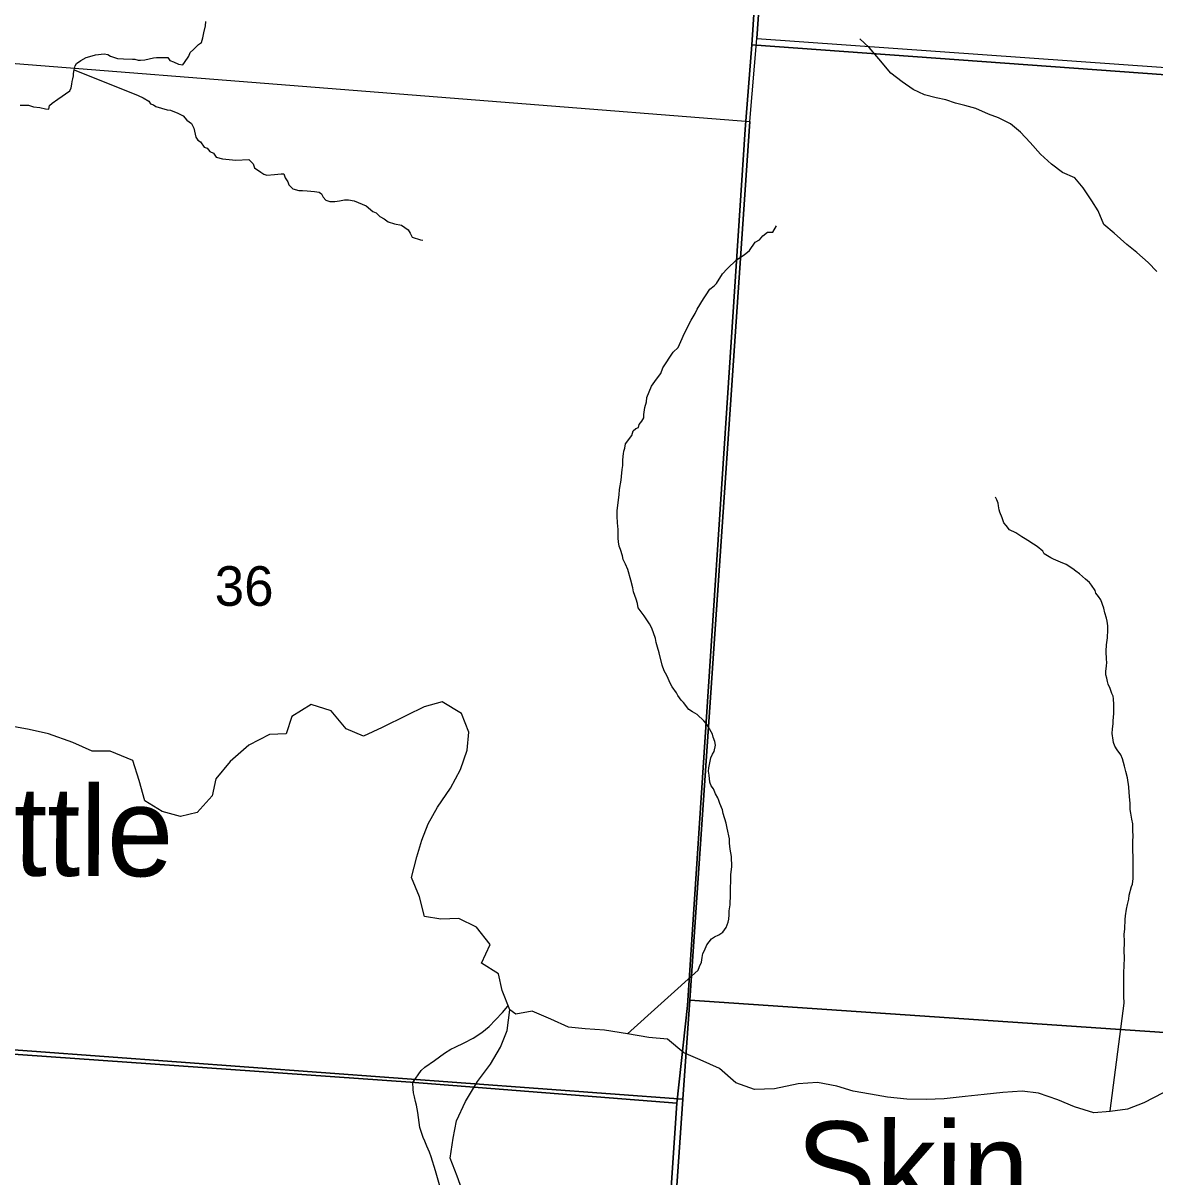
# Model space of a CAD drawing. Extents: x 0 to 34, y 0 to 22.
# Drawn here: x 6.132 to 7.329, y 19.223 to 20.443 of the extents above; entities that cross this region are included whole.
import ezdxf

# ---------------------------------------------------------------- set-up
doc = ezdxf.new("R2010")
doc.units = 0
for name, color, linetype in [('GM_X_Corporation', 7, 'Continuous'), ('GM_X_Minor_River', 7, 'Continuous'), ('GM_X_Minor_River_Text', 7, 'Continuous'), ('GM_X_Section_Text', 7, 'Continuous'), ('GM_X_Township_Road', 7, 'Continuous')]:
    doc.layers.add(name, color=color, linetype=linetype)

msp = doc.modelspace()

# ---------------------------------------------------------------- linework, layer by layer
at = {"layer": 'GM_X_Corporation'}
for points in [[(6.9348, 20.9), (2.1, 20.9), (2.1, 19.6396), (2.105, 19.6393), (2.5886, 19.6074), (3.0215, 19.5789), (3.8201, 19.5262), (3.8692, 19.5228), (4.8375, 19.4557), (5.0201, 19.4401), (5.6539, 19.3859), (5.9419, 19.3649), (6.5423, 19.3229), (6.824, 19.3005), (6.835, 19.4037), (6.8961, 20.3303), (6.9032, 20.4198)], [(6.9414, 20.9), (5.9334, 20.9), (5.901, 20.4176), (6.9011, 20.3385), (6.9084, 20.4264)], [(8.9, 20.2763), (8.9, 20.9), (6.9348, 20.9), (6.9032, 20.4198), (8.0028, 20.34), (8.3805, 20.3169), (8.59, 20.3005)], [(8.4295, 20.9), (6.9414, 20.9), (6.9084, 20.4264), (8.0074, 20.3484), (8.3851, 20.3217)], [(6.9084, 20.4264), (8.0074, 20.3484), (7.9347, 19.3346), (6.8376, 19.4096), (6.9011, 20.3385)], [(6.9011, 20.3385), (6.8376, 19.4096), (6.8303, 19.3047), (5.8355, 19.3781), (5.901, 20.4176)], [(8.9, 16.2015), (8.9, 20.2763), (8.59, 20.3005), (8.3805, 20.3169), (8.0028, 20.34), (6.9032, 20.4198), (6.8961, 20.3303), (6.835, 19.4037), (6.824, 19.3005), (6.7876, 18.7583), (6.7629, 18.3924), (6.7536, 18.2991), (6.7043, 17.4985), (6.6962, 17.3669), (6.6852, 17.2401), (6.6249, 16.3344), (7.5782, 16.28), (7.7162, 16.2721), (7.873, 16.2628)], [(7.9347, 19.3346), (7.864, 18.3242), (6.7676, 18.3985), (6.8303, 19.3047), (6.8376, 19.4096)], [(5.8355, 19.3781), (6.8303, 19.3047), (6.7676, 18.3985), (6.7615, 18.3053), (5.775, 18.3681)]]:
    msp.add_lwpolyline(points, close=True, dxfattribs=at)
msp.add_lwpolyline([(6.7043, 17.4985), (6.7536, 18.2991), (6.7629, 18.3924), (6.7876, 18.7583), (6.824, 19.3005), (6.5423, 19.3229), (5.9419, 19.3649), (5.6539, 19.3859), (5.0201, 19.4401), (4.8375, 19.4557), (3.8692, 19.5228), (3.8201, 19.5262), (3.0215, 19.5789), (2.5886, 19.6074), (2.105, 19.6393), (2.1, 19.6396), (2.1, 16.1353)], dxfattribs=at)
at = {"layer": 'GM_X_Minor_River'}
for points in [[(6.1294, 20.3559), (6.1382, 20.3558), (6.1434, 20.3541), (6.1502, 20.3533), (6.1563, 20.352), (6.1597, 20.3516), (6.1605, 20.3554), (6.1632, 20.358), (6.1693, 20.3621), (6.182, 20.371), (6.1832, 20.3744), (6.184, 20.3781), (6.1844, 20.3808), (6.1849, 20.3838), (6.1857, 20.3869), (6.1857, 20.3895), (6.1865, 20.3933), (6.1877, 20.3975), (6.1889, 20.4001), (6.1935, 20.4031), (6.1993, 20.4064), (6.2054, 20.4082), (6.2092, 20.4092), (6.2183, 20.4102), (6.222, 20.4094), (6.225, 20.4078), (6.2322, 20.4054), (6.2386, 20.4049), (6.2481, 20.4044), (6.2507, 20.4044), (6.2541, 20.4035), (6.2568, 20.4035), (6.2613, 20.4038), (6.2705, 20.4059), (6.2735, 20.4062), (6.278, 20.4062), (6.2856, 20.4064), (6.2878, 20.4033), (6.2916, 20.4018), (6.2969, 20.3994), (6.3014, 20.3986), (6.303, 20.4012), (6.3076, 20.4079), (6.3092, 20.4117), (6.3127, 20.4147), (6.3181, 20.4199), (6.3211, 20.4221), (6.3227, 20.4271), (6.3236, 20.4324), (6.3252, 20.4399), (6.3257, 20.4445)], [(7.3315, 20.1801), (7.3224, 20.1896), (7.3103, 20.2002), (7.2997, 20.2085), (7.2865, 20.2206), (7.2755, 20.2297), (7.2694, 20.2441), (7.2626, 20.2547), (7.2535, 20.2684), (7.2448, 20.279), (7.2316, 20.2847), (7.2202, 20.2937), (7.2085, 20.304), (7.1975, 20.3165), (7.1873, 20.3275), (7.1767, 20.3362), (7.1642, 20.3426), (7.1536, 20.3464), (7.14, 20.3525), (7.1283, 20.3555), (7.1184, 20.3582), (7.1082, 20.3616), (7.098, 20.3638), (7.0859, 20.3669), (7.0738, 20.3726), (7.0621, 20.3805), (7.05, 20.3896), (7.0375, 20.4048), (7.0273, 20.4169), (7.0174, 20.426)], [(6.1865, 20.3933), (6.2542, 20.3663), (6.2595, 20.3636), (6.2655, 20.36), (6.2673, 20.3574), (6.2703, 20.3562), (6.273, 20.3546), (6.2847, 20.351), (6.2884, 20.3505), (6.296, 20.3474), (6.3016, 20.3446), (6.3057, 20.34), (6.3105, 20.3365), (6.3131, 20.3315), (6.3152, 20.322), (6.3174, 20.3189), (6.32, 20.317), (6.3241, 20.3116), (6.3271, 20.3104), (6.3301, 20.3069), (6.3338, 20.305), (6.3368, 20.3011), (6.3432, 20.2991), (6.3576, 20.2977), (6.3712, 20.2986), (6.3757, 20.294), (6.3771, 20.2898), (6.3839, 20.2851), (6.3869, 20.2828), (6.3903, 20.282), (6.3982, 20.2826), (6.4054, 20.2832), (6.4081, 20.2832), (6.4095, 20.279), (6.4125, 20.2748), (6.4136, 20.2717), (6.4176, 20.2675), (6.4241, 20.2658), (6.4278, 20.2658), (6.4328, 20.2653), (6.4407, 20.2648), (6.4456, 20.2639), (6.4482, 20.262), (6.4497, 20.2585), (6.4527, 20.2555), (6.4568, 20.2542), (6.4621, 20.2542), (6.467, 20.2548), (6.4724, 20.2559), (6.4765, 20.2558), (6.4826, 20.2546), (6.4954, 20.2494), (6.5025, 20.2436), (6.5058, 20.242), (6.5099, 20.2382), (6.5144, 20.2358), (6.5185, 20.2327), (6.5253, 20.2303), (6.5325, 20.229), (6.5362, 20.2267), (6.5396, 20.224), (6.5418, 20.2205), (6.544, 20.2163), (6.5527, 20.2135), (6.5552, 20.2131)], [(6.7653, 19.9634), (6.7662, 19.9706), (6.7666, 19.9748), (6.7667, 19.9801), (6.7672, 19.9846), (6.7676, 19.9873), (6.7677, 19.9899), (6.7689, 19.9933), (6.7697, 19.9979), (6.7763, 20.0065), (6.7775, 20.0114), (6.7806, 20.014), (6.7833, 20.0151), (6.7841, 20.0181), (6.7868, 20.0219), (6.7888, 20.0253), (6.7888, 20.0287), (6.7901, 20.0363), (6.7917, 20.0423), (6.7922, 20.0469), (6.7969, 20.0589), (6.8023, 20.0661), (6.807, 20.0721), (6.809, 20.0781), (6.8199, 20.0946), (6.8253, 20.0995), (6.828, 20.1059), (6.832, 20.1149), (6.839, 20.1285), (6.8433, 20.1356), (6.8453, 20.1402), (6.8519, 20.1511), (6.855, 20.1552), (6.8589, 20.1612), (6.8632, 20.1649), (6.8659, 20.1672), (6.8721, 20.1777), (6.8771, 20.1829), (6.8868, 20.1922), (6.8952, 20.1978), (6.9006, 20.2023), (6.9068, 20.2109), (6.9114, 20.2135), (6.9149, 20.2176), (6.9199, 20.2217), (6.9252, 20.2216), (6.9291, 20.2284)], [(6.7715, 19.3738), (6.8463, 19.4413), (6.8479, 19.445), (6.8498, 19.4496), (6.8507, 19.4545), (6.8515, 19.4587), (6.8531, 19.462), (6.8555, 19.4681), (6.8605, 19.4745), (6.8636, 19.4763), (6.8681, 19.4785), (6.8724, 19.4815), (6.8759, 19.4863), (6.8782, 19.492), (6.8787, 19.495), (6.8791, 19.4996), (6.8792, 19.5041), (6.8801, 19.5102), (6.8806, 19.5212), (6.881, 19.5425), (6.8819, 19.5504), (6.8817, 19.5615), (6.8803, 19.5691), (6.8797, 19.5755), (6.8794, 19.5801), (6.8769, 19.5912), (6.8759, 19.5965), (6.873, 19.6068), (6.872, 19.6106), (6.8694, 19.6175), (6.8684, 19.6206), (6.8673, 19.6236), (6.8647, 19.6275), (6.8625, 19.6328), (6.8603, 19.6363), (6.8589, 19.6401), (6.8579, 19.6473), (6.8575, 19.6515), (6.8576, 19.6553), (6.8597, 19.6659), (6.8617, 19.6697), (6.8632, 19.6723), (6.8649, 19.6791), (6.8642, 19.6829), (6.8623, 19.6875), (6.8616, 19.6909), (6.8569, 19.699), (6.8547, 19.7021), (6.8524, 19.7048), (6.8453, 19.7114), (6.8405, 19.7145), (6.8367, 19.7168), (6.8308, 19.7241), (6.8286, 19.7268), (6.8249, 19.7318), (6.8234, 19.7345), (6.819, 19.7407), (6.8171, 19.7441), (6.8131, 19.7529), (6.8106, 19.7579), (6.8084, 19.7636), (6.8052, 19.7766), (6.8034, 19.7827), (6.802, 19.7877), (6.8013, 19.7919), (6.7973, 19.8029), (6.7948, 19.8075), (6.7892, 19.816), (6.7829, 19.8245), (6.7823, 19.829), (6.7808, 19.8336), (6.7779, 19.8413), (6.7773, 19.8454), (6.7751, 19.8535), (6.7719, 19.8649), (6.7694, 19.8706), (6.7672, 19.8756), (6.7665, 19.8794), (6.7643, 19.8859), (6.7629, 19.8897), (6.7622, 19.8943), (6.7619, 19.8981), (6.7617, 19.9072), (6.761, 19.9141), (6.7608, 19.9213), (6.7609, 19.9274), (6.7627, 19.9437), (6.7632, 19.9494), (6.7649, 19.9592), (6.7653, 19.9634)], [(7.2109, 19.8844), (7.2049, 19.8891), (7.2012, 19.8918), (7.1952, 19.8957), (7.1922, 19.8973), (7.1888, 19.8996), (7.1824, 19.9035), (7.1757, 19.907), (7.1723, 19.9113), (7.1697, 19.9143), (7.1679, 19.9197), (7.1654, 19.9254), (7.1647, 19.9281), (7.164, 19.9323), (7.1637, 19.935), (7.1622, 19.9384), (7.1608, 19.9413)], [(7.2822, 19.2925), (7.2968, 19.4062), (7.2965, 19.4138), (7.2967, 19.426), (7.2965, 19.4363), (7.2966, 19.4401), (7.2971, 19.4442), (7.2973, 19.4556), (7.297, 19.4602), (7.2972, 19.472), (7.2969, 19.4788), (7.2978, 19.4849), (7.298, 19.4947), (7.2984, 19.4985), (7.2993, 19.5057), (7.3005, 19.5106), (7.3017, 19.5163), (7.3022, 19.5205), (7.3046, 19.5296), (7.3058, 19.5322), (7.3063, 19.5383), (7.3066, 19.5561), (7.3063, 19.5622), (7.306, 19.5668), (7.3061, 19.5713), (7.3062, 19.5782), (7.3063, 19.5823), (7.3061, 19.5896), (7.3062, 19.596), (7.3051, 19.601), (7.3041, 19.6071), (7.3034, 19.6112), (7.3031, 19.6177), (7.3028, 19.6211), (7.3022, 19.6291), (7.3019, 19.6352), (7.3006, 19.6447), (7.2988, 19.6512), (7.2974, 19.6569), (7.2953, 19.6646), (7.2934, 19.6688), (7.2897, 19.6742), (7.2872, 19.678), (7.2857, 19.6818), (7.2854, 19.6845), (7.2844, 19.6913), (7.2845, 19.6963), (7.2853, 19.7016), (7.2854, 19.705), (7.2859, 19.7126), (7.286, 19.7221), (7.2858, 19.7282), (7.2854, 19.7308), (7.284, 19.7339), (7.2822, 19.7392), (7.28, 19.7438), (7.2793, 19.7465), (7.2786, 19.7499), (7.2775, 19.7534), (7.2776, 19.7575), (7.2784, 19.7625), (7.2785, 19.767), (7.2782, 19.7697), (7.2779, 19.7784), (7.2784, 19.7853), (7.2793, 19.7928), (7.2795, 19.8012), (7.2796, 19.8054), (7.2789, 19.8103), (7.2782, 19.8134), (7.2764, 19.8191), (7.2753, 19.8241), (7.2721, 19.8328), (7.2699, 19.8363), (7.2669, 19.8398), (7.2662, 19.8428), (7.2625, 19.8482), (7.2603, 19.8513), (7.2562, 19.8548), (7.2498, 19.8602), (7.2457, 19.8633), (7.2427, 19.8656), (7.2356, 19.8703), (7.2296, 19.8727), (7.2221, 19.8759), (7.2195, 19.8774), (7.2123, 19.8813), (7.2109, 19.8844)], [(6.5999, 19.1999), (6.5916, 19.2234), (6.5841, 19.2424), (6.5872, 19.2636), (6.591, 19.2818), (6.6002, 19.3023), (6.6131, 19.3235), (6.6268, 19.3417), (6.6374, 19.3598), (6.6443, 19.3773), (6.6474, 19.3992), (6.6391, 19.4198), (6.6354, 19.4372), (6.6173, 19.4486), (6.6264, 19.4683), (6.6121, 19.4866), (6.5932, 19.4957), (6.5743, 19.495), (6.5569, 19.4981), (6.5516, 19.5186), (6.5434, 19.5391), (6.5487, 19.5611), (6.5541, 19.5785), (6.561, 19.596), (6.5709, 19.6134), (6.5846, 19.6338), (6.5952, 19.6535), (6.6021, 19.674), (6.6037, 19.6929), (6.5962, 19.7127), (6.5758, 19.7249), (6.5568, 19.7196), (6.5379, 19.7106), (6.5121, 19.6977), (6.4924, 19.6887), (6.4742, 19.6963), (6.4584, 19.7154), (6.4372, 19.7222), (6.4167, 19.7094), (6.4106, 19.6912), (6.3932, 19.6905), (6.3712, 19.6792), (6.3515, 19.6618), (6.3363, 19.6437), (6.3325, 19.6255), (6.3165, 19.6081), (6.2991, 19.6036), (6.2794, 19.6089), (6.2613, 19.6204), (6.2553, 19.6416), (6.2485, 19.6629), (6.2244, 19.6728), (6.2054, 19.6729), (6.185, 19.682), (6.1593, 19.6912), (6.1389, 19.6958), (6.1177, 19.6997)], [(6.8138, 19.3684), (6.7942, 19.37), (6.7715, 19.3738), (6.7473, 19.3777), (6.7268, 19.3793), (6.7094, 19.3809), (6.6905, 19.3893), (6.6709, 19.3977), (6.6534, 19.3947), (6.6474, 19.3992)], [(7.3382, 19.3115), (7.3178, 19.3009), (7.3003, 19.2941), (7.2822, 19.2919), (7.2648, 19.2904), (7.2443, 19.2966), (7.2269, 19.3042), (7.2065, 19.3111), (7.1891, 19.3134), (7.1687, 19.312), (7.149, 19.3098), (7.1286, 19.3075), (7.1066, 19.3053), (7.0877, 19.3046), (7.0672, 19.3047), (7.0468, 19.307), (7.0286, 19.3101), (7.0105, 19.3132), (6.9931, 19.3186), (6.9727, 19.3224), (6.9522, 19.321), (6.9272, 19.3157), (6.906, 19.315), (6.8864, 19.3219), (6.869, 19.3371), (6.8486, 19.3463), (6.8312, 19.3539), (6.8138, 19.3684)]]:
    msp.add_lwpolyline(points, dxfattribs=at)
at = {"layer": 'GM_X_Township_Road'}
for points in [[(6.5447, 19.3223), (6.5534, 19.335), (6.5573, 19.3385), (6.5675, 19.3456), (6.5781, 19.3533), (6.585, 19.3575), (6.5894, 19.3598), (6.5988, 19.3642), (6.6083, 19.3692), (6.6175, 19.3754), (6.6254, 19.3815), (6.6319, 19.3886), (6.6395, 19.3963), (6.6451, 19.403)], [(6.5749, 19.2067), (6.5686, 19.2289), (6.5641, 19.2439), (6.5622, 19.2489), (6.5596, 19.2552), (6.5575, 19.2603), (6.5555, 19.2644), (6.5522, 19.275), (6.5498, 19.2906), (6.5485, 19.2984), (6.5476, 19.3024), (6.5463, 19.3074), (6.5455, 19.3114), (6.5451, 19.3152), (6.5447, 19.3223)]]:
    msp.add_lwpolyline(points, dxfattribs=at)

# ---------------------------------------------------------------- texts
at = {"layer": 'GM_X_Minor_River_Text'}
for s, rotation, p in [('Little', 359.7569, (6.0239, 19.5415)), ('Skin', 359.754, (6.9499, 19.1867))]:
    msp.add_text(s, height=0.09469, rotation=rotation, dxfattribs=at).set_placement(p)
at = {"layer": 'GM_X_Section_Text'}
msp.add_text('36', height=0.04186, rotation=0, dxfattribs=at).set_placement((6.3351, 19.8265))

doc.saveas('drawing.dxf')
